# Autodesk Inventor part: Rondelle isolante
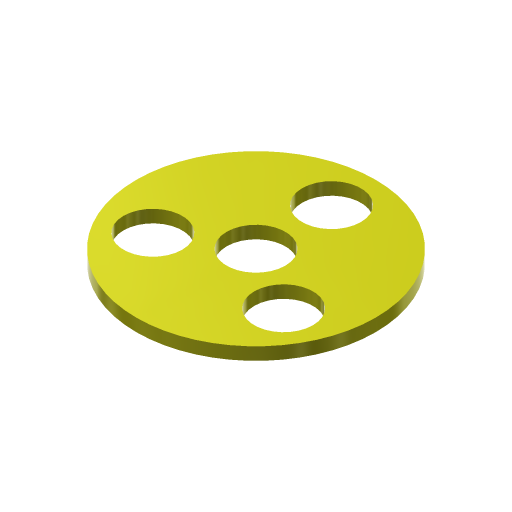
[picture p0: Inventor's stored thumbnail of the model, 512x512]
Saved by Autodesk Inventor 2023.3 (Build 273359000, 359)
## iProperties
Created: 2016-03
Part Number: Rondelle isolante
Material: Générique
Document SubType Name: Modeling
Designer: sbaumgartn
Density: 1 g/cm^3
Appearance: Lisse - Jaune
Author: sbaumgartn
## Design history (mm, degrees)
sketch "Esquisse1"
  geometry: C1 r 14.25 at (0, 0); 1 further point
  constraints: 1 centre point, 1 coincident
  dimensions: "d0" = 28.5 diameter of C1
extrude "Extrusion1" new body sketch "Esquisse1" distance "d2" = 1.5; taper "d3" = 0 deg
sketch "Esquisse3"
  geometry: C1 r 14.25 at (0, 0) reference; C2 r 3.5 at (0, 9); C3 r 3.5 at (0, 0); C4 r 3.5 at (-7.794, -4.5); C5 r 3.5 at (7.794, -4.5)
  constraints: 4 centre point, 1 coincident, 7 other
  dimensions: "d6" = 7 diameter of C2; "d8" = 9 distance of C2.centre C1.centre; "d9" = 7 diameter of C3; "d12" = 360 deg dimension on C1.centre C2.centre (derived)
extrude "Extrusion2" cut sketch "Esquisse3" extent not by distance; stored distance "d14" = 2; taper "d15" = 0 deg
node "Solide1"
